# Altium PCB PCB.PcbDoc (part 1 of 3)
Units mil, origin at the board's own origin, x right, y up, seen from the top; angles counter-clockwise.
Board outline 5900 x 2310 mil, 2 copper layers (Top Layer, Bottom Layer), stack 62 mil thick; 158 components, 83 nets, 407 pads, 547 vias.
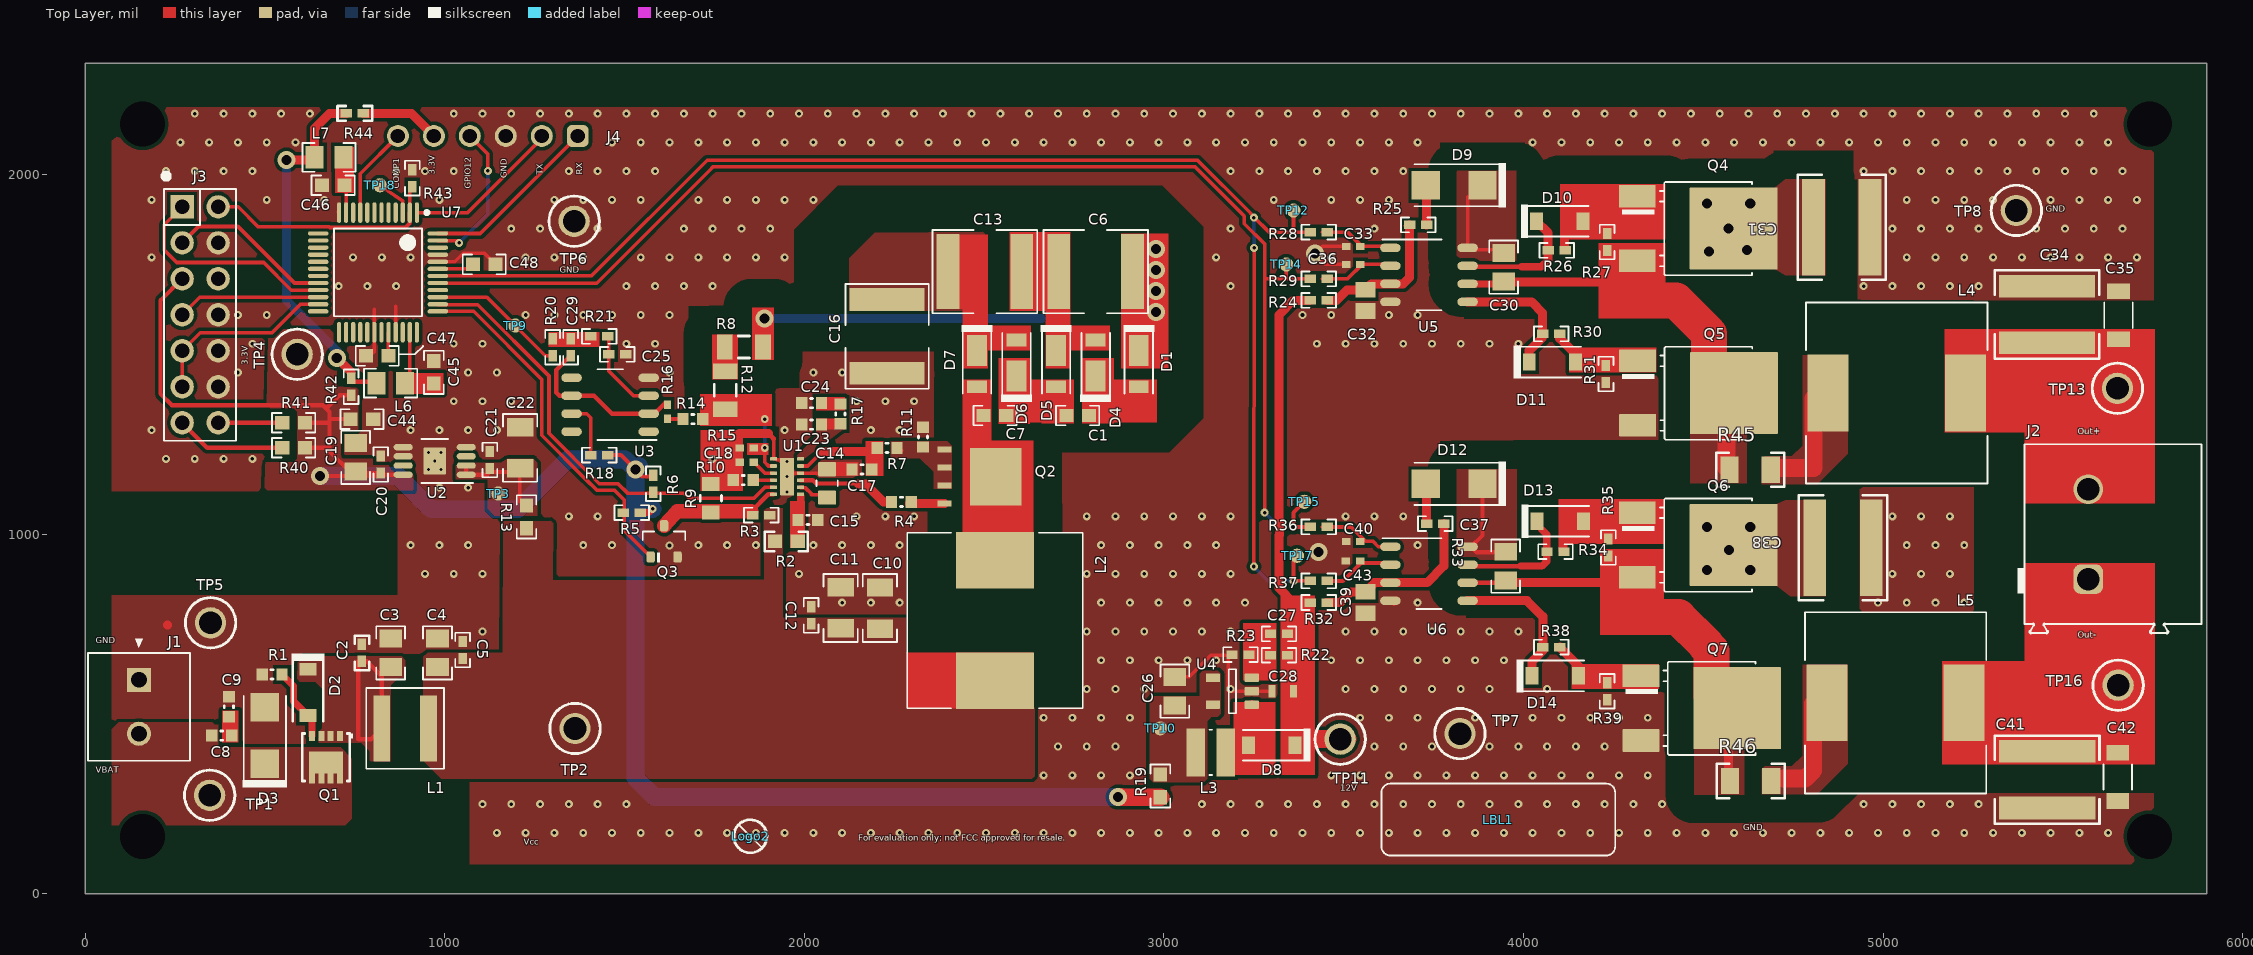
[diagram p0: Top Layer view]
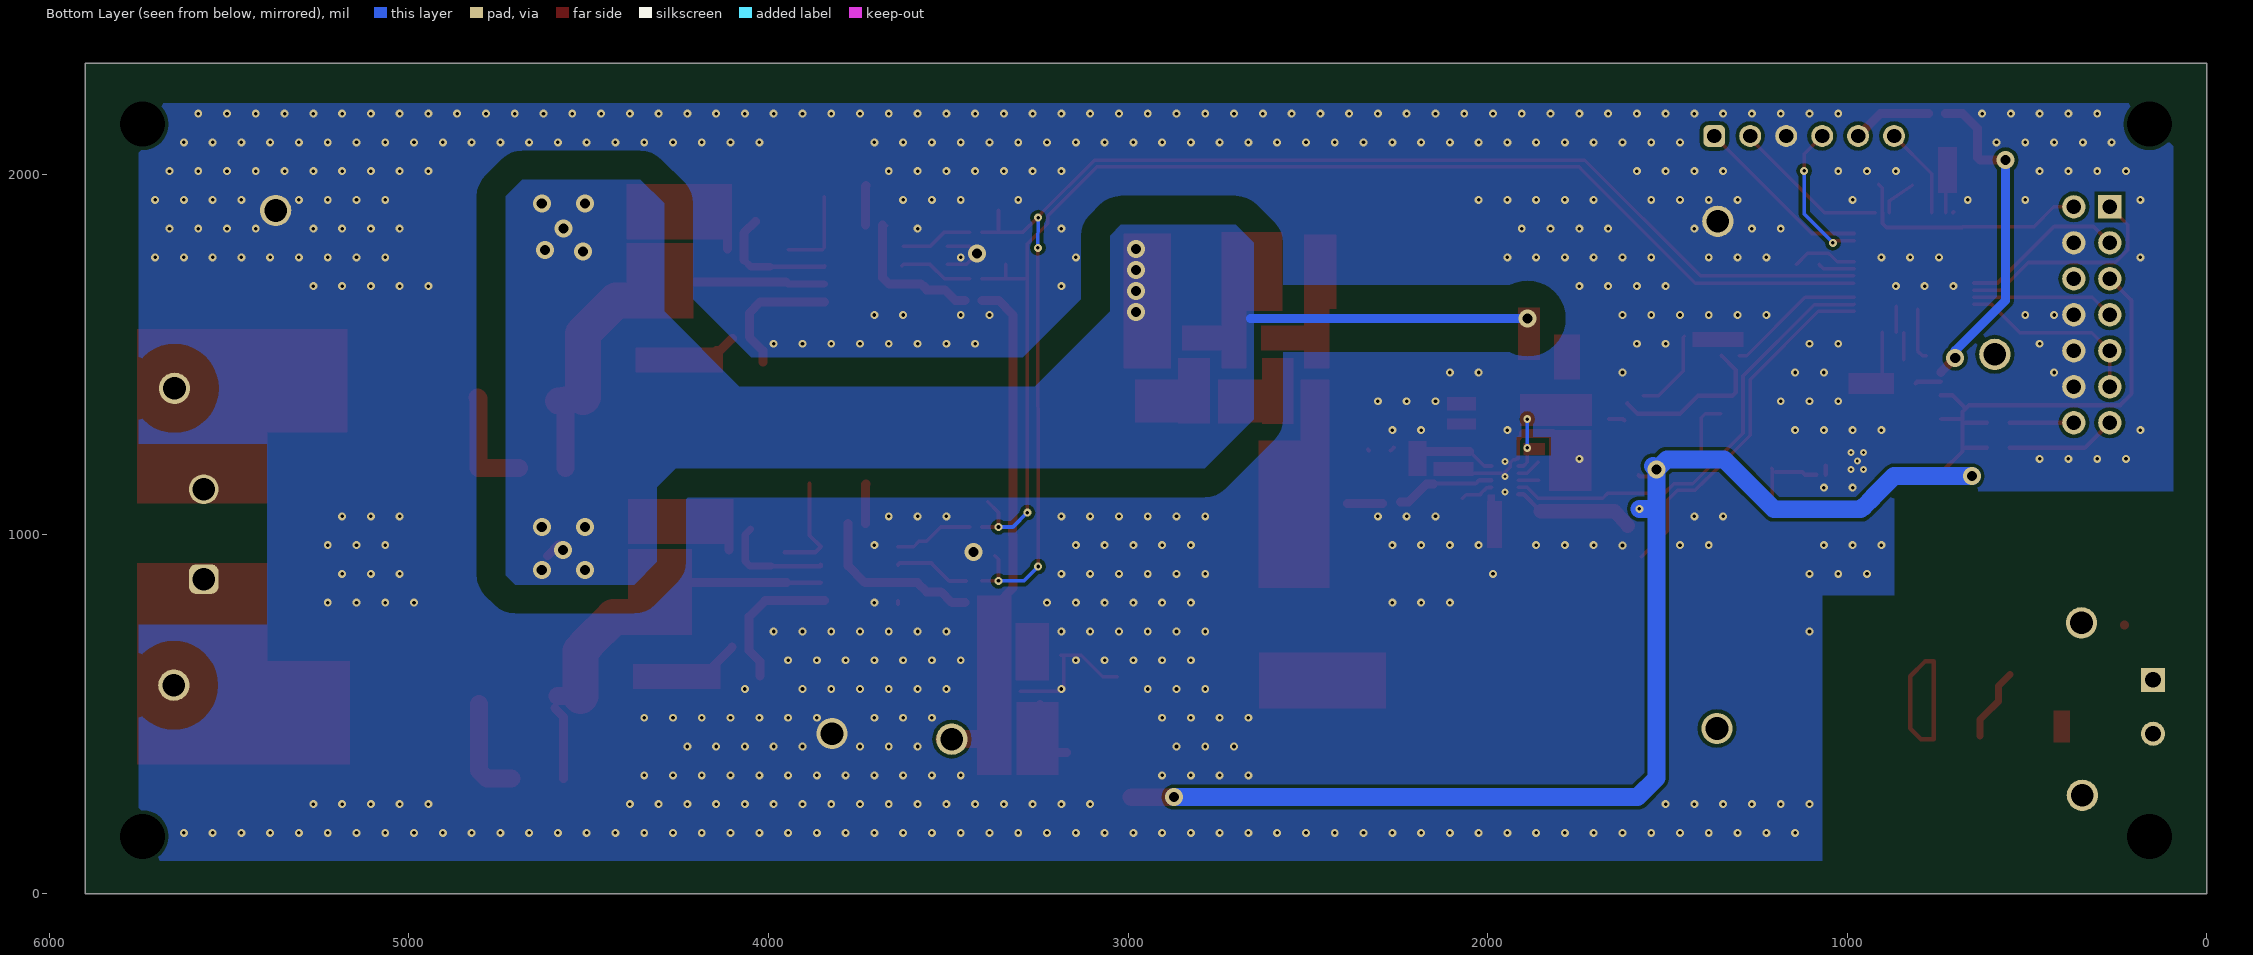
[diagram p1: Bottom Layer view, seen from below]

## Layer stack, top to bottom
Top Solder: solder mask 0.4, Solder Resist, Dk 3.5
Top Layer: signal copper 1.4
Dielectric1: core 59.2, FR-4, Dk 4.8
Bottom Layer: signal copper 1.4
Bottom Solder: solder mask 0.4, Solder Resist, Dk 3.5

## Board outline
0,0 0,2310 5900,2310 5900,0

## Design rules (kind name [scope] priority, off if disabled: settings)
AcuteAngle [All] p1: minimum=4.50000000000000E+0001 checktracksonly=FALSE
AssemblyTestPointUsage [All] p1: valid=2
BoardOutlineClearance BoardOutlineClearance_MountingHoles [OnCopper and InComponentClass('Mounting Holes')] p1: gap=40 ignorepadtopadclearanceinfootprint=FALSE
BoardOutlineClearance BoardOutlineClearance_Poly [OnCopper and IsPoly] p2: gap=25 ignorepadtopadclearanceinfootprint=FALSE
BoardOutlineClearance [OnCopper and Not InComponentClass('Logo') and not InComponentClass('FiducialMark') and not InRegion(1000,500,4000,800) and not InPoly] p3: gap=75 ignorepadtopadclearanceinfootprint=FALSE
Clearance Clearance_HV_Signal_GND [InNetClass('HV_Signal') vs InNet('GND')] p1: gap=80 ignorepadtopadclearanceinfootprint=FALSE
Clearance Clearance_HV_LV_Bridge [InNet('HV') vs InNetClass('LV_Bridge')] p2: gap=80 ignorepadtopadclearanceinfootprint=FALSE
Clearance Clearance_HV_Bridge_LV_Bridge [InNetClass('HV_Bridge') vs InNetClass('LV_Bridge')] p3: gap=80 ignorepadtopadclearanceinfootprint=FALSE
Clearance Clearance_HV_Bridge_GND [InNetClass('HV_Bridge') vs InNet('GND')] p4: gap=80 ignorepadtopadclearanceinfootprint=FALSE
Clearance Clearance_HV_CP_GND [InNetClass('HV_CP') vs InNet('GND')] p5: gap=80 ignorepadtopadclearanceinfootprint=FALSE
Clearance Clearance_HV_GND [InNet('HV') vs InNet('GND')] p6: gap=90 ignorepadtopadclearanceinfootprint=FALSE
Clearance Clearance_Keepouts [((IsTrack Or IsArc) And Not InPoly) And IsFree and IsKeepOut vs ((IsTrack Or IsArc) And Not InPoly) And IsFree and IsKeepOut] p7: gap=0 ignorepadtopadclearanceinfootprint=FALSE
Clearance Clearance_Poly [InPolygon] p8: gap=10 ignorepadtopadclearanceinfootprint=FALSE
Clearance Clearance_FiducialMark [IsKeepOut and InComponentClass('FiducialMark') vs IsPad and InComponentClass('FiducialMark')] p9: gap=0 ignorepadtopadclearanceinfootprint=FALSE
Clearance [All] p10: gap=7.87 ignorepadtopadclearanceinfootprint=FALSE except(0: Arc-Hole Track-Hole SMDPad-Hole THPad-Hole Via-Hole Fill-Hole Poly-Hole Region-Hole Text-Hole)
ComponentClearance ComponentClearance_MountingHoles_FiducialMarks [InComponentClass('Mounting Holes') vs InComponentClass('FiducialMark')] p1: gap=50 collisioncheckmode=3 verticalgap=10 showdistances=FALSE
ComponentClearance ComponentClearance_Shunt [InComponentClass('Header') vs InComponentClass('Shunt')] p2: gap=0 collisioncheckmode=3 verticalgap=0 showdistances=FALSE
ComponentClearance ComponentClearance_Logo [InComponentClass('Logo')] p3: gap=50 collisioncheckmode=3 verticalgap=10 showdistances=FALSE
ComponentClearance ComponentClearance_ScrewToNut [(HasFootprint('NY PMS 440 0025 PH')) vs (HasFootprint('Keystone_1902C'))] p4: gap=5 collisioncheckmode=3 verticalgap=10 showdistances=FALSE
ComponentClearance ComponentClearance_MountingHoles [InComponentClass('Mounting Holes')] p5: gap=250 collisioncheckmode=3 verticalgap=100000 showdistances=FALSE
ComponentClearance ComponentClearance_SmallPassives [HasFootprint('0201*') or HasFootprint('0402*') or HasFootprint('0508') or HasFootprint('0603*') or HasFootprint('0612') or HasFootprint('0805*') or HasFootprint('0815*') or HasFootprint('0830*') or HasFootprint('1206*') or HasFootprint('1210*') or HasFootprint('1808*') or HasFootprint('1812*') or HasFootprint('1825*') or HasFootprint('2010*') or HasFootprint('2220*') or HasFootprint('2225*') or HasFootprint('2512*') or HasFootprint('2728*') or HasFootprint('3518*') vs HasFootprint('0201*') or HasFootprint('0402*') or HasFootprint('0508') or HasFootprint('0603*') or HasFootprint('0612') or HasFootprint('0805*') or HasFootprint('0815*') or HasFootprint('0830*') or HasFootprint('1206*') or HasFootprint('1210*') or HasFootprint('1808*') or HasFootprint('1812*') or HasFootprint('1825*') or HasFootprint('2010*') or HasFootprint('2220*') or HasFootprint('2225*') or HasFootprint('2512*') or HasFootprint('2728*') or HasFootprint('3518*')] p6: gap=14.96 collisioncheckmode=3 verticalgap=10 showdistances=FALSE
ComponentClearance ComponentClearance_THtoSMT [IsThruComponent vs IsSMTComponent] p7: gap=40 collisioncheckmode=3 verticalgap=30 showdistances=FALSE
ComponentClearance ComponentClearance_THtoTH [IsThruComponent vs IsThruComponent] p8: gap=30 collisioncheckmode=3 verticalgap=30 showdistances=FALSE
ComponentClearance [All] p9: gap=30 collisioncheckmode=3 verticalgap=10 showdistances=FALSE
DiffPairsRouting [All] p1: maxlimit=100 minlimit=10 mostfreqgap=10 toplayer_minwidth=15 toplayer_maxwidth=15 toplayer_prefwidth=15 bottomlayer_minwidth=15 bottomlayer_maxwidth=15 bottomlayer_prefwidth=15 maxuncoupledlength=1000
FabricationTestPointUsage TestPointUsage [All] p1: valid=2 allowmultiple=FALSE
FabricationTestpoint Testpoint [All] p1: side=3 testpointundercomponent=TRUE minsize=40 maxsize=100 preferedsize=60 minholesize=0 maxholesize=40 preferedholesize=32 testpointgrid=1 allowsidetop=TRUE allowsidebottom=TRUE usegrid=TRUE gridtolerance=0.01
FanoutControl Fanout_LCC [IsLCC] p1: bgadir=Out bgaviamode=Centered fanoutstyle=Auto fanoutdirection=Alternating viagrid=1 // Fanout_LCC (Default Rule)
FanoutControl Fanout_BGA [IsBGA] p2: bgadir=Out bgaviamode=Centered fanoutstyle=Auto fanoutdirection=Alternating viagrid=1 // Fanout_BGA (Default Rule)
FanoutControl Fanout_Default [All] p4: bgadir=Out bgaviamode=Centered fanoutstyle=Auto fanoutdirection=Alternating viagrid=1 // Fanout_Default (Default Rule)
FanoutControl Fanout_Small [(CompPinCount < 5)] p5: bgadir=Out bgaviamode=Centered fanoutstyle=Auto fanoutdirection=OutThenIn viagrid=1 // Fanout_Small (Default Rule)
HoleSize [All] p1: absolutevalues=TRUE maxlimit=251 minlimit=7.87 maxpercent=80.000 minpercent=20.000
MinimumAnnularRing MinimumAnnularRing_ThermalPadVias [IsVia and InAnyComponent] p1: minimumring=5.91
MinimumAnnularRing [All] p2: minimumring=5
MinimumSolderMaskSliver MinimumSolderMaskSliver_Logo [InComponentClass('Logo') vs InComponentClass('Logo')] p1: minsoldermaskwidth=0.7
MinimumSolderMaskSliver [All] p2: minsoldermaskwidth=3.94
PlaneClearance [All] p1: clearance=10
PlaneConnect [All] p1: planeconnectstyle=Relief reliefexpansion=10 reliefentries=4 reliefconductorwidth=10 reliefairgap=10
PolygonConnect [All] p1: connectstyle=Direct reliefconductorwidth=10 reliefentries=4 polygonreliefangle="90 Angle" airgapwidth=10
RoutingVias ThermalPadVias [IsVia and InAnyComponent] p1: holewidth=7.87 width=19.68 viastyle="Through Hole" minholewidth=7.87 minwidth=19.68 maxholewidth=12.99 maxwidth=23.62
RoutingVias [All] p2: holewidth=16 width=34 viastyle="Through Hole" minholewidth=7.87 minwidth=20 maxholewidth=40 maxwidth=65
SilkToBoardRegionClearance [Not ((IsComment or IsDesignator) And (Hide <> 'False')) and not InRegion(1000,500,4000,800)] p1:
SilkToSilkClearance SilkToSilkClearance_Pb-FreeLogo [(HasFootprint('Pb-Free_Overlay_Medium') OR HasFootprint('Pb-Free_Overlay_Small')) vs (HasFootprint('Pb-Free_Overlay_Medium') OR HasFootprint('Pb-Free_Overlay_Small'))] p1: silktosilkclearance=0
SilkToSilkClearance [All] p2: silktosilkclearance=1
SilkToSolderMaskClearance SilkToComponentPadClearance [(IsPad or IsFill or IsRegion) and InAnycomponent] p1: minsilkscreentomaskgap=3 clearancetoexposedcopper=TRUE
SilkToSolderMaskClearance "Silk to Solder Mask Opening" [All] p2: minsilkscreentomaskgap=4 clearancetoexposedcopper=FALSE
SolderMaskExpansion [All] p1: expansion=1.97
Width [All] p1: maxlimit=100 minlimit=6 preferedwidth=10 checkconnectedcopper=TRUE
14 further rules are at their usual default settings.

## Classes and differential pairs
net class HV_Bridge: NetC30_1 NetC30_2 NetC37_1 NetC37_2 NetD10_1 NetD10_2 NetD13_1 NetD13_2
component class Pg3: C44 C45 C46 C47 C48 J3 J4 L6 L7 R40 R41 R42 R43 R44 TP18 U7
component class Pg2: C30 C31 C32 C33 C34 C35 C36 C37 C38 C39 C40 C41 C42 C43 D9 D10 D11 D12 D13 D14 J2 L4 L5 Q4 Q5 Q6 R24 R25 R26 R27 R28 R29 R30 R31 R32 R33 R34 R35 R36 R37 R38 R39 R45 R46 TP12 TP13 TP14 TP15 TP16 TP17 U5 U6
component class Pg1: C1 C2 C3 C4 C5 C6 C7 C8 C9 C10 C11 C12 C13 C14 C15 C16 C17 C18 C19 C20 C21 C22 C23 C24 C25 C26 C27 C28 C29 D1 D2 D3 D4 D5 D6 D7 D8 J1 L1 L2 L3 Q1 Q2 Q3 Q? R1 R2 R3 R4 R5 R6 R7 R8 R9 R10 R11 R12 R13 R14 R15 R16 R17 R18 R19 R20 R21 R22 R23 R? TP1 TP2 TP3 TP4 TP5 TP6 TP7 TP8 TP9 TP10 TP11 U1 U2 U3 U4
component class EVM_Hardware: LBL1 Logo1 Logo2 Logo3 ZZ1 ZZ2 ZZ3 ZZ4
component class AssemblyNote: ZZ1 ZZ2 ZZ3 ZZ4
component class Label: LBL1
component class Header: J3 J4
net class HV_CP: HV NetC1_1 NetC1_2 NetC6_2 NetC7_2 NetC13_2 NetR8_1
net class LV_Bridge: GND NetD11_2 NetD14_2
net class LV_Bridge_Pins: GND NetD11_1 NetD14_1
net class HV_Signal: NetC34_1 NetC41_1 NetL4_1 NetL5_1

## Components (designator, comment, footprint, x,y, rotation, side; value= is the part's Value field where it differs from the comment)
C1 "HMK107B7104KAHT" 0603 2760,1330 r180 top value=0.1uF
C2 "GCM155R71H104KE02D" 0402 770,670 r90 top value=0.1uF
C3 "CGA4J3X7R1H684K125AB" 0805_HV 850,670 r90 top value=0.68uF
C4 "CGA4J3X7R1H684K125AB" 0805_HV 980,670 r90 top value=0.68uF
C5 "GCM155R71H104KE02D" 0402 1050,678 r90 top value=0.1uF
C6 "CGA9M3X7S2A685K200KB" 2220_220 2810,1730 r180 top value=6.8uF
C7 "HMK107B7104KAHT" 0603 2530,1330 r180 top value=0.1uF
C8 "CGA3E2X7R2A472K080AA" 0603L 380,440 r0 top value=4700pF
C9 "CGA3E2X7R2A472K080AA" 0603L 400,520 r270 top value=4700pF
C10 "CGA5L3X5R1H106M160AB" 1206 2210.32,794.5 r90 top value=10uF
C11 "CGA5L3X5R1H106M160AB" 1206 2101,795 r90 top value=10uF
C12 "GCM155R71H104KE02D" 0402 2018.65,774.12 r90 top value=0.1uF
C13 "CGA9M3X7S2A685K200KB" 2220_220 2502.05,1730 r180 top value=6.8uF
C14 "CGA4J3X7R1H105K125AB" 0805_HV1 2063.3,1141.13 r270 top value=1uF
C15 "CGA3E2NP01H101J080AA" 0603L 2010,1040 r0 top value=100pF
C16 "CGA9M3X7S2A685K200KB" 2220_220 2230,1550 r270 top value=6.8uF
C17 "CGA3E2NP01H101J080AA" 0603L 2160,1180 r180 top value=100pF
C18 "CGA2B3X7R1H103K050BB" 0402L 1840,1200 r180 top value=0.01uF
C19 "CGA4J1X7R1V475K125AC" 0805_HV 752.6,1213.62 r90 top value=4.7uF
C20 "GCM155R71H104KE02D" 0402 822.28,1193.62 r90 top value=0.1uF
C21 "GCM155R71H104KE02D" 0402 1125.5,1206.24 r90 top value=0.1uF
C22 "CGA5L3X5R1H106M160AB" 1206 1210,1240 r90 top value=10uF
C23 "CGA3E2X7R2A223K080AA" 0603L 2020,1304.43 r180 top value=0.022uF
C24 "CGA3E3X7S2A333K080AB" 0603L 2020,1364.43 r180 top value=0.033uF
C25 "CGA2B3X7R1H103K050BB" 0402 1480,1500 r0 top value=0.01uF
C26 "CGA4J1X7R1V475K125AC" 0805_HV 3030,563.29 r90 top value=4.7uF
C27 "CGA2B3X7R1H103K050BB" 0402 3320,722.5 r180 top value=0.01uF
C28 "CGA3E1X7R1E105K080AC" 0603S 3330,563.29 r180 top value=1uF
C29 "CGA2B3X7R1H223K050BB" 0402 1350,1520 r90 top value=0.022uF
C30 "CGA4J2X7R1H224K125AA" 0805_HV 3944.34,1742.25 r90 top value=0.22uF
C31 "1825PC105KAT1A" 1825_254 4884.5,1853.5 r0 top value=1uF
C32 "CGA4J1X7R1E475K125AC" 0805L 3560,1650 r270 top value=4.7uF
C33 "C0402C330J5GACAUTO" 0402L 3526.37,1800 r180 top value=33pF
C34 "1825PC105KAT1A" 1825_254 5455,1611 r90 top value=1uF
C35 "CGA5L4X7T2W104M160AA" 1206_180 5654,1608.5 r90 top value=0.1uF
C36 "C0402C330J5GACAUTO" 0402L 3526.37,1750 r180 top value=33pF
C37 "CGA4J2X7R1H224K125AA" 0805_HV 3950,911.12 r90 top value=0.22uF
C38 "1825PC105KAT1A" 1825_254 4888,962 r0 top value=1uF
C39 "CGA4J1X7R1E475K125AC" 0805L 3560,810 r270 top value=4.7uF
C40 "C0402C330J5GACAUTO" 0402L 3526.37,980 r180 top value=33pF
C41 "1825PC105KAT1A" 1825_254 5455.5,317.5 r270 top value=1uF
C42 "CGA5L4X7T2W104M160AA" 1206_180 5652,325 r270 top value=0.1uF
C43 "C0402C330J5GACAUTO" 0402L 3525.75,925.03 r180 top value=33pF
C44 "CL10B105KP8VPNC" 0603 770,1320 r0 top value=1uF
C45 "GCM188R70J225KE22D" 0603 970,1450 r90 top value=2.2uF
C46 "GCM188R70J225KE22D" 0603 690,1970 r180 top value=2.2uF
C47 "GCM188R70J225KE22D" 0603 812.47,1495.75 r180 top value=2.2uF
C48 "GCM188R70J225KE22D" 0603 1110,1750 r0 top value=2.2uF
D1 "DFLS1100Q-7" PowerDI123 2930,1460 r270 top value=100V
D2 "BZT52C16-7-F" SOD-123 620,560 r270 top value=16V
D3 "P4SMA18CA-E3/61" SMA 500,440 r90 top value=18V
D4 "DFLS1100Q-7" PowerDI123 2810,1490 r90 top value=100V
D5 "DFLS1100Q-7" PowerDI123 2700,1460 r270 top value=100V
D6 "DFLS1100Q-7" PowerDI123 2590,1490 r90 top value=100V
D7 "DFLS1100Q-7" PowerDI123 2480,1460 r270 top value=100V
D8 "MBR0520LT1G" SOD-123 3300,413.29 r180 top value=20V
D9 "MURA160T3G" SMA 3806.77,1970 r180 top value=600V
D10 "BAT46W-E3-08" SOD-123 4100,1870 r0 top value=100V
D11 "BAT46W-E3-08" SOD-123 4080.03,1478.5 r0 top value=100V
D12 "MURA160T3G" SMA 3806.77,1140 r180 top value=600V
D13 "BAT46W-E3-08" SOD-123 4101.5,1036 r0 top value=100V
D14 "BAT46W-E3-08" SOD-123 4088,605.98 r0 top value=100V
J1 "1727010" PhoenixConact_1727010 150,520 r270 top
J2 "OSTT7020150" On-Shore_OSTT7020150 5570,1000 r90 top
J3 "PEC07DAAN" CONN_PEC07DAAN 320,1610 r270 top
J4 "TSW-106-07-T-S" Samtec_TSW-106-07-T-S 1120,2107.12 r180 top
L1 "XAL5030-222MEB" XAL5030 890,460 r0 top value=2.2uH
L2 "MSS1260T-273MLB" MSS1260T 2530,760 r90 top value=27uH
L3 "78438335220" WE-MAIA_3015 3130,393.29 r0 top value=22uH
L4 "SRR1260A-331K" SRR1260A 5037.5,1392.5 r0 top value=330uH
L5 "SRR1260A-331K" SRR1260A 5034,531 r0 top value=330uH
L6 "742792063" 0805_HV 850,1420 r180 top value="60 ohm"
L7 "782853221" 0805_HV 678.35,2047.8 r180 top value="220 ohm"
LBL1 "THT-14-423-10" Label_650x200 3929.5,206.5 r180 top
Logo2 "Pb-Free Symbol" Pb-Free_Overlay_Small 1850,160 r0 top
Logo3 "FCC disclaimer" FCC_disclaimer 830,2810 r0 top
Q1 "DMP3035SFG-7" PowerDI3333-8 670,380 r270 top value=-30V
Q2 "SQJA68EP-T1_GE3" PowerPAK_SO-8L 2500,1160 r0 top value=100V
Q3 "BSS806NEH6327XTSA1" SOT-23L 1610,980 r90 top value=20V
Q4 "IPD5N25S3430ATMA1" DPAK 4450,1850 r0 top value=250V
Q5 "IPD5N25S3430ATMA1" DPAK 4450.86,1392.24 r0 top value=250V
Q6 "IPD5N25S3430ATMA1" DPAK 4450,970 r0 top value=250V
Q7 "IPD5N25S3430ATMA1" DPAK 4460,516.22 r0 top value=250V
R1 "CRCW06031K50FKEA" 0603L 520,610 r0 top value=1.50k
R2 "CRCW060310R0FKEAHP" 0603 1950,980 r0 top value=10.0
R3 "CRCW04026K34FKED" 0402 1880.5,1053 r0 top value=6.34k
R4 "RCS06030000Z0EA" 0603L 2270,1090 r0 top value=0
R5 "CRCW0402511KFKED" 0402 1520,1060 r0 top value=511k
R6 "CRCW0402511KFKED" 0402 1580,1140 r90 top value=511k
R7 "CRCW060310R0FKEAHP" 0603L 2230,1240 r0 top value=10.0
R8 "ERJ-8ENF2003V" 1206L 1832,1520.5 r0 top value=200k
R9 "ERJ-6ENF1691V" 0805_HV1 1740,1100 r270 top value=1.69k
R10 "CRCW06039K09FKEA" 0603L 1830,1150 r0 top value=9.09k
R11 "ERJ-L03KF50MV" 0603L 2330,1270 r270 top value=0.05
R12 "ERJ-8ENF1023V" 1206L 1780,1400 r90 top value=102k
R13 "RCS06030000Z0EA" 0603 1227.5,1048 r270 top value=0
R14 "CRCW06034K02FKEA" 0603L 1690,1320 r180 top value=4.02k
R15 "ERJ-2RKF2401X" 0402L 1840,1240 r0 top value=2.40k
R16 "CRCW04020000Z0EDHP" 0402L 1620,1340 r270 top value=0
R17 "CRCW060319K6FKEA" 0603L 2100,1334.43 r270 top value=19.6k
R18 "CRCW04020000Z0EDHP" 0402 1430,1220 r0 top value=0
R19 "RCS06030000Z0EA" 0603 2990,300 r270 top value=0
R20 "CRCW04027K87FKED" 0402 1300,1520 r90 top value=7.87k
R21 "CRCW040214K7FKED" 0402 1430,1550 r0 top value=14.7k
R22 "CRCW04021M50FKED" 0402 3320,663.29 r0 top value=1.50Meg
R23 "CRCW0402174KFKED" 0402 3212.79,665 r0 top value=174k
R24 "CRCW04020000Z0EDHP" 0402 3430,1650 r180 top value=0
R25 "CRCW04022R21FKED" 0402 3706.77,1860 r0 top value=2.21
R26 "CRCW04023R32FKED" 0402 4092,1789 r0 top value=3.32
R27 "CRCW040210K2FKED" 0402 4232,1812.5 r90 top value=10.2k
R28 "CRCW040249R9FKED" 0402 3430,1840 r0 top value=49.9
R29 "CRCW040249R9FKED" 0402 3430,1710 r0 top value=49.9
R30 "CRCW04023R32FKED" 0402 4077,1557 r0 top value=3.32
R31 "CRCW040210K2FKED" 0402 4229,1445.5 r90 top value=10.2k
R32 "CRCW04020000Z0EDHP" 0402 3430,810 r180 top value=0
R33 "CRCW04022R21FKED" 0402 3754.5,1029.5 r180 top value=2.21
R34 "CRCW04023R32FKED" 0402 4088.81,951.5 r0 top value=3.32
R35 "CRCW040210K2FKED" 0402 4235.73,963 r90 top value=10.2k
R36 "CRCW040249R9FKED" 0402 3430,1020 r0 top value=49.9
R37 "CRCW040249R9FKED" 0402 3430,870 r0 top value=49.9
R38 "CRCW04023R32FKED" 0402 4077,686 r0 top value=3.32
R39 "CRCW040210K2FKED" 0402 4232,562.97 r90 top value=10.2k
R40 "CRCW06034K70JNEA" 0603 580,1240 r0 top value=4.7k
R41 "CRCW06034K70JNEA" 0603 580,1310 r0 top value=4.7k
R42 "CRCW04020000Z0EDHP" 0402 740,1410 r90 top value=0
R43 "RMCF0402FT2K20" 0402 910,1990 r270 top value=2.20k
R44 "CRCW04021K02FKED" 0402 750,2170 r0 top value=1.02k
R45 "CRCW120618R0JNEA" 1206 4629.5,1179 r0 top value=18
R46 "CRCW120618R0JNEA" 1206 4631,313.5 r0 top value=18
TP1 "5010" Keystone5010 346.5,274 r270 top
TP2 "5010" Keystone5010 1362.5,459.69 r90 top
TP3 "TP_SM_1MM" TP_SM_1MM 1149,1113 r270 top
TP4 "5010" Keystone5010 590,1500 r270 top
TP5 "5011" Keystone5011 349,753.5 r0 top
TP6 "5011" Keystone5011 1360,1870 r0 top
TP7 "5011" Keystone5011 3823,445.5 r0 top
TP8 "5011" Keystone5011 5370,1900 r0 top
TP9 "TP_SM_1MM" TP_SM_1MM 1196.38,1580 r90 top
TP10 "TP_SM_1MM" TP_SM_1MM 2990,460 r0 top
TP11 "5010" Keystone5010 3490,430 r180 top
TP12 "TP_SM_1MM" TP_SM_1MM 3360,1900 r90 top
TP13 "5127" Keystone5127 5651,1405.5 r0 top
TP14 "TP_SM_1MM" TP_SM_1MM 3340,1750 r90 top
TP15 "TP_SM_1MM" TP_SM_1MM 3390,1090 r90 top
TP16 "5127" Keystone5127 5653,580 r0 top
TP17 "TP_SM_1MM" TP_SM_1MM 3370,940 r90 top
TP18 "TP_SM_1MM" TP_SM_1MM 820,1970 r90 top
U1 "LM5155QDSSTQ1" DSS0012C 1952.05,1160 r180 top
U2 "TPS7B8233QDGNRQ1" DGN0008D_N 972.28,1203.62 r180 top
U3 "TLV271QDRQ1" D0008A_N 1460,1360 r180 top
U4 "TPS61041QDBVRQ1" DBV0005A_N 3190,563.29 r180 top
U5 "UCC27712QDRQ1" D0008A_N 3736.77,1720.87 r0 top
U6 "UCC27712QDRQ1" D0008A_N 3736.77,890 r0 top
U7 "TMS320F28027PTQ" PT0048A_N 814.52,1727.8 r270 top
ZZ1 "This Assembly Note is for PCB labels only" AssemblyNoteLabel 4843.5,5612 r90 top
ZZ2 "These assemblies are ESD sensitive, ESD precautions shall be observed." AssemblyNote 4816,5725.5 r0 top
ZZ3 "These assemblies must be clean and free from flux and all contaminants. Use of no clean flux is not acceptable." AssemblyNote 4816,5839.5 r0 top
ZZ4 "These assemblies must comply with workmanship standards IPC-A-610 Class 2, unless otherwise specified." AssemblyNote 4814,5943 r0 top

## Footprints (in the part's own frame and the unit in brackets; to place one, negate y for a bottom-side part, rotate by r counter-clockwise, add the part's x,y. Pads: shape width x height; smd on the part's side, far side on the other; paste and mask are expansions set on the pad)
0402 [mm] "0402 from SM-752 data"
  rect 0.8x0.6 smd: 1(-0.6,0) 2(0.6,0)
  silkscreen extent -1.22,-0.52 1.22,0.52, body extent -0.55,-0.3 0.55,0.3, height 0.6
0402L [mm] "0402 from SM-752 data"
  rect 0.6x0.5 smd: 1(-0.5,0) 2(0.5,0)
  body extent -0.55,-0.3 0.55,0.3, height 0.6
0603 [mm] "0603 from SM-752 data"
  rect 1x0.95 smd: 1(-0.8,0) 2(0.8,0)
  silkscreen extent -1.52,-0.69 1.52,0.69, body extent -0.87,-0.47 0.87,0.47, height 1
0603L [mm] "0603 from SM-752 data"
  rect 0.8x0.85 smd: 1(-0.7,0) 2(0.7,0)
  silkscreen extent -0.07,-0.33 0.07,0.33, body extent -0.87,-0.47 0.87,0.47, height 1
0603S [mil]
  rect 20x35 smd: 1(-30,0) 2(30,0)
  body extent -34,-19 34,19, height 39
0805_HV [mil] "0805 with 30mil clearance between pads"
  rect 50x63 smd: 1(-40,0) 2(40,0)
  silkscreen extent -74,-40 74,40, body extent -43,-29 43,29, height 57
0805_HV1 [mm] "Custom footprint based on analyzing multiple manufacturer recommendations"
  rrect10% 1x1.25 smd: 1(-1,0) 2(1,0)
  silkscreen extent -0.2,-0.75 0.2,0.75, body extent -1.1,-0.72 1.1,0.73, height 1.45
0805L [mm] "0805 from SM-752 data"
  rect 1.1x1.4 smd: 1(-0.75,0) 2(0.75,0)
  body extent -1.1,-0.72 1.1,0.72, height 1.45
1206 [mm] "1206 from SM-752 data"
  rect 1.3x1.85 smd: 1(-1.45,0) 2(1.45,0)
  silkscreen extent -2.4,-1.21 2.4,1.21, body extent -1.7,-0.9 1.7,0.9, height 1.35
1206_180 [mm] "1206_180"
  rect 1.1x1.6 smd: 1(-1.7,0) 2(1.7,0)
  silkscreen extent -0.9,-1 0.9,1, body extent -1.75,-0.95 1.75,0.95, height 1.8
1206L [mm] "1206 from SM-752 data"
  rect 1.1x1.75 smd: 1(-1.35,0) 2(1.35,0)
  silkscreen extent -0.4,-0.77 0.4,0.77, body extent -1.7,-0.9 1.7,0.9, height 1.35
1825_254 [mm] "Chip Capacitor, Body 4.5x6.4mm, IPC Medium Density"
  rect 1.6x6.8 smd: 1(-2,0) 2(2,0)
  silkscreen extent -3.11,-3.7 3.11,3.7, body extent -2.4,-3.4 2.4,3.4, height 2.54
2220_220 [mm] "Chip Capacitor, Body 5.7x5.0mm, IPC Medium Density"
  rect 1.6x5.3 smd: 1(-2.6,0) 2(2.6,0)
  silkscreen extent -3.69,-2.94 3.69,2.94, body extent -2.95,-2.62 2.95,2.62, height 2.2
AssemblyNote [mil] "Assembly Note"
AssemblyNoteLabel [mil] "Assembly Note for PCB Labels"
CONN_PEC07DAAN [mm] "SULLINS"
  rect 1.65x1.65 hole 1.016 mask+0: 1(-7.62,-1.27)
  round 1.65 hole 1.016 mask+0: 2(-7.62,1.27) 3(-5.08,-1.27) 4(-5.08,1.27) 5(-2.54,-1.27) 6(-2.54,1.27) 7(0,-1.27) 8(0,1.27) 9(2.54,-1.27) 10(2.54,1.27) 11(5.08,-1.27) 12(5.08,1.27) 13(7.62,-1.27) 14(7.62,1.27)
  silkscreen extent -9.99,-2.6 8.89,2.54, body extent -8.95,-2.6 8.95,2.6, height 8.38
D0008A_N [mm] "SOIC, 8-Leads, Body 4.9x3.9mm, Pitch 1.27mm, IPC Medium Density"
  oval 1.45x0.6 smd: 1(-2.725,1.905) 2(-2.725,0.635) 3(-2.725,-0.635) 4(-2.725,-1.905) 5(2.725,-1.905) 6(2.725,-0.635) 7(2.725,0.635) 8(2.725,1.905)
  silkscreen extent -3.3,-2.5 0.9,2.5, body extent -3,-2.45 3,2.45, height 1.63
DBV0005A_N [mm] "SOT23, 5-Leads, Body 2.9x1.6mm, Pitch 0.95mm, Lead Span 2.8mm, IPC Medium Density"
  rrect17% 1x0.6 smd: 1(-1.375,0.95) 2(-1.375,0) 3(-1.375,-0.95) 4(1.375,-0.95) 5(1.375,0.95)
  silkscreen extent -0.25,-1.55 0.25,1.55, body extent -1.42,-1.46 1.42,1.46, height 1.09
DGN0008D_N [mm] "TSOP, 8-Leads, Body 3x3mm, Pitch 0.65mm, Thermal Pad 1.89x1.57mm, IPC Medium Density"
  rrect100% 1.35x0.45 smd: 1(-2.225,0.975) 2(-2.225,0.325) 3(-2.225,-0.325) 4(-2.225,-0.975) 5(2.225,-0.975) 6(2.225,-0.325) 7(2.225,0.325) 8(2.225,0.975)
  rrect6% 1.57x1.89 smd: 9(0,0)
  silkscreen extent -2.73,-1.55 0.95,1.55, body extent -2.46,-1.5 2.46,1.5, height 1.1
DPAK [mm] "D-PAK, 3-Pads, Body 6.22x6.73mm (max), TO-252AA using nominal STEP model"
  rrect6% 2.6x1.6 smd: 1(-3.4,2.28) 3(-3.4,-2.28)
  rrect2% 6.2x5.8 smd paste-2.9: 4(3.4,0)
  silkscreen extent -4.5,-3.3 4.7,3.28, body extent -3.86,-3.29 5.84,3.29, height 2.48
DSS0012C [mm] "WSON-12"
  rrect40% 0.5x0.25 smd: 1(-0.95,1.25) 2(-0.95,0.75) 3(-0.95,0.25) 4(-0.95,-0.25) 5(-0.95,-0.75) 6(-0.95,-1.25) 7(0.95,-1.25) 8(0.95,-0.75) 9(0.95,-0.25) 10(0.95,0.25) 11(0.95,0.75) 12(0.95,1.25)
  rrect11% 0.95x1.17 on Top Paste: 13(0,0.685) 13(0,-0.685)
  rrect11% 1x2.65 smd paste-0.5: 13(0,0)
  body extent -1,-1.5 1,1.5, height 0.81
FCC_disclaimer [mil]
Keystone5010 [mil] "Keystone Multipurpose loops"
  round 87 hole 63: 1(0,0)
  silkscreen extent -70,-70 70,70, body extent -63,-63 63,62, height 319
Keystone5011 [mil] "Keystone Multipurpose loops"
  round 87 hole 63: 1(0,0)
  silkscreen extent -70,-70 70,70, body extent -63,-63 63,62, height 319
Keystone5127 [mil] "Keystone Multipurpose loops"
  round 87 hole 63: 1(0,0)
  silkscreen extent -70,-70 70,70, body extent -63,-63 63,62, height 319
Label_650x200 [mil] "Thermal Transfer Label"
  round 1 on Mech13: 0(0,0)
  silkscreen extent -325,-100 325,100, body extent -325,-100 325,100, height 1
MSS1260T [mm] "COILCRAFT"
  rect 4x5.5 smd: 1(-4.25,0) 2(4.25,0)
  silkscreen extent -6.2,-6.2 6.2,6.2, body extent -6.15,-6.15 6.15,6.15, height 6.2
On-Shore_OSTT7020150 [mm] "Terminal Block, 6.35mm, 2x1, TH"
  rrect50% 2.1x2.1 hole 1.6: 1(-3.175,0)
  round 2.1 hole 1.6: 2(3.175,0)
  silkscreen extent -6.98,-8 6.35,5, body extent -6.98,-8 6.35,4.5, height 21.5
Pb-Free_Overlay_Small [mil]
  silkscreen extent -46,-46 46,46
PhoenixConact_1727010 [mm]
  rect 1.7x1.7 hole 1.1: 1(-1.905,0)
  round 1.7 hole 1.1: 2(1.905,0)
  silkscreen extent -4.8,-3.6 3.81,3.6, body extent -3.81,-3.6 3.81,3.7, height 8.52
PowerDI123 [mm] "Diodes Inc recommended land pattern, document number DS30628 Rev. 6-2"
  rect 2.2x1.4 smd: 1(-1.275,0)
  rect 0.9x1.4 smd: 2(1.275,0)
  silkscreen extent -3.1,-1.09 1.76,1.09, body extent -2.38,-0.97 1.52,0.96, height 1
PowerDI3333-8 [mm] "SMD, 8-Leads, Body 3.3x3.3mm, Pitch 0.65mm"
  rect 0.7x0.42 smd: 1(-1.5,0.975) 2(-1.5,0.325) 3(-1.5,-0.325) 4(-1.5,-0.975) 5(1.5,-0.975) 6(1.5,-0.325) 7(1.5,0.325) 8(1.5,0.975)
  rect 1.55x2.37 smd: 9(0.375,0)
  silkscreen extent -1.68,-1.68 1.68,1.9, body extent -1.68,-1.68 1.68,1.68, height 0.86
PowerPAK_SO-8L [mm] "based on Vishay recommended land pattern Document 63818 Feb 7, 2012"
  rect 1x0.41 smd: 1(-2.805,1.905) 2(-2.805,0.635) 3(-2.805,-0.635) 4(-2.805,-1.905)
  rect 3.63x4.061 smd: 5(0.805,0)
  Top Layer region: -0.298,-2.64 0.298,-2.64 0.298,-2.03 -0.298,-2.03
  Top Layer region: -0.297,2.03 0.298,2.03 0.298,2.64 -0.297,2.64
  Top Layer region: 2.615,-2.5 3.125,-2.5 3.125,2.5 2.615,2.5
  body extent -3.07,-2.57 3.08,2.57, height 1.21
PT0048A_N [mm] "Thin QFP, 48-Leads, Body 7x7mm, Pitch 0.5mm, IPC Medium Density"
  oval 1.45x0.3 smd: 1(-4.225,2.75) 2(-4.225,2.25) 3(-4.225,1.75) 4(-4.225,1.25) 5(-4.225,0.75) 6(-4.225,0.25) 7(-4.225,-0.25) 8(-4.225,-0.75) 9(-4.225,-1.25) 10(-4.225,-1.75) 11(-4.225,-2.25) 12(-4.225,-2.75) 25(4.225,-2.75) 26(4.225,-2.25) 27(4.225,-1.75) 28(4.225,-1.25) 29(4.225,-0.75) 30(4.225,-0.25) 31(4.225,0.25) 32(4.225,0.75) 33(4.225,1.25) 34(4.225,1.75) 35(4.225,2.25) 36(4.225,2.75)
  oval 0.3x1.45 smd: 13(-2.75,-4.225) 14(-2.25,-4.225) 15(-1.75,-4.225) 16(-1.25,-4.225) 17(-0.75,-4.225) 18(-0.25,-4.225) 19(0.25,-4.225) 20(0.75,-4.225) 21(1.25,-4.225) 22(1.75,-4.225) 23(2.25,-4.225) 24(2.75,-4.225) 37(2.75,4.225) 38(2.25,4.225) 39(1.75,4.225) 40(1.25,4.225) 41(0.75,4.225) 42(0.25,4.225) 43(-0.25,4.225) 44(-0.75,4.225) 45(-1.25,4.225) 46(-1.75,4.225) 47(-2.25,4.225) 48(-2.75,4.225)
  silkscreen extent -4.35,-3.1 3.1,3.58, body extent -4.51,-4.51 4.51,4.51, height 1.5
Samtec_TSW-106-07-T-S [mm] "Samtec 100mil, 6x1, 230 mil above insulator"
  rrect50% 1.55x1.55 hole 1.02: 1(-6.35,0)
  round 1.55 hole 1.02: 2(-3.81,0) 3(-1.27,0) 4(1.27,0) 5(3.81,0) 6(6.35,0)
  body extent -7.75,-1.27 7.62,1.27, height 8.39
SMA [mm] "Molded Diode, 2-Leads, Body 4.3x2.6mm, IPC Medium Density, based on OnSemi component dimensions and land pattern"
  rect 2x2 smd: 1(-2,0) 2(2,0)
  silkscreen extent -3.66,-1.57 2.79,1.57, body extent -2.6,-1.3 2.6,1.3, height 2.42
SOD-123 [mm] "On Semi recommended land pattern"
  rect 0.915x1.22 smd: 1(-1.637,0) 2(1.637,0)
  silkscreen extent -2.74,-1.17 2.03,1.17, body extent -1.93,-0.9 1.93,0.9, height 1.35
SOT-23L [mm] "SOT23, 3-Leads, Body 2.9x1.3mm, Pitch 0.95mm, Lead Span 2.5mm, IPC High Density"
  rrect50% 0.8x0.6 smd: 1(-1.1,0.95) 2(-1.1,-0.95) 3(1.1,0)
  silkscreen extent -1.5,-1.5 0.7,1.5, body extent -1.16,-1.45 1.21,1.45, height 1
SRR1260A [mil] "Bourns UL"
  rect 114x213 smd: 1(-191,0) 2(191,0)
  silkscreen extent -252,-252 252,252, body extent -252,-252 252,252, height 236
TP_SM_1MM [mm] "1mm Test Point, SMT"
  round 1 smd paste-0.5: 1(0,0)
WE-MAIA_3015 [mm] "SMD, 2-Leads, Body 3x3mm"
  rect 1.3x3.4 smd: 1(-1.05,0) 2(1.05,0)
  silkscreen extent -0.1,-1.6 0.1,1.6, body extent -1.6,-1.6 1.6,1.6, height 1.5
XAL5030 [mil] "Coilcraft XAL5030 12/12/11"
  rect 46x183 smd: 1(-65,0) 2(65,0)
  silkscreen extent -108,-112 108,112, body extent -108,-112 108,112, height 122

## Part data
C1 C7: library part CMP-0081011-1, "CAP, CERM, 0.1 µF, 100 V,+/- 10%, X7R, AEC-Q200 Grade 1, 0603", Cap_Case=0603, Manufacturer="Taiyo Yuden", Supplier Part Number 1=587-6009-1-ND, TempCo=X7R, Tolerance_%=10%, Value2=100V, ValueDisplayed=0.1µF
C2 C5 C12 C20 C21: library part CMP-0006356-2, "CAP, CERM, 0.1 uF, 50 V, +/- 10%, X7R, AEC-Q200 Grade 1, 0402", Cap_Case=0402, Manufacturer=MuRata, Supplier Part Number 1=490-10672-1-ND, TempCo=X7R, Tolerance_%=10%, Value1=Unknown, Value2=50V, ValueDisplayed=0.1uF
C3 C4: library part CMP-0007979-2, "CAP, CERM, 0.68 uF, 50 V, +/- 10%, X7R, AEC-Q200 Grade 1, 0805", Cap_Case=0805, Manufacturer=TDK, Supplier Part Number 1=445-6960-1-ND, TempCo=X7R, Tolerance_%=10%, Value1="0.011711 ohm", Value2=50V, ValueDisplayed=0.68uF
C6 C13 C16: library part CMP-0009407-2, "CAP, CERM, 6.8 uF, 100 V, +/- 10%, X7S, AEC-Q200 Grade 1, 2220", Cap_Case=2220_220, Manufacturer=TDK, Supplier Part Number 1=445-13153-1-ND, TempCo=X7S, Tolerance_%=10%, Value1="0.003492 ohm", Value2=100V, ValueDisplayed=6.8uF
C8 C9: library part CMP-0007088-4, "CAP, CERM, 4700 pF, 100 V, +/- 10%, X7R, AEC-Q200 Grade 1, 0603", Cap_Case=0603, Manufacturer=TDK, Supplier Part Number 1=445-5810-1-ND, TempCo=X7R, Tolerance_%=10%, Value1="0.469862 ohm", Value2=100V, ValueDisplayed=4700pF
C10 C11 C22: library part CMP-0008785-2, "CAP, CERM, 10 uF, 50 V, +/- 20%, X5R, AEC-Q200 Grade 3, 1206", Cap_Case=1206, Manufacturer=TDK, Supplier Part Number 1=445-12883-1-ND, TempCo=X5R, Tolerance_%=20%, Value1=Unknown, Value2=50V, ValueDisplayed=10uF
C14: library part CMP-0007976-2, "CAP, CERM, 1 uF, 50 V, +/- 10%, X7R, AEC-Q200 Grade 1, 0805", Cap_Case=0805, Manufacturer=TDK, Supplier Part Number 1=445-6961-1-ND, TempCo=X7R, Tolerance_%=10%, Value1="0.008782 ohm", Value2=50V, ValueDisplayed=1uF
C15 C17: library part CMP-0007075-4, "CAP, CERM, 100 pF, 50 V, +/- 5%, C0G/NP0, AEC-Q200 Grade 0, 0603", Cap_Case=0603, Manufacturer=TDK, Supplier Part Number 1=445-12386-1-ND, TempCo=C0G/NP0, Tolerance_%=5%, Value1=Unknown, Value2=50V, ValueDisplayed=100pF
C18 C25 C27: library part CMP-0006324-2, "CAP, CERM, 0.01 uF, 50 V, +/- 10%, X7R, AEC-Q200 Grade 1, 0402", Cap_Case=0402, Manufacturer=TDK, Supplier Part Number 1=445-6893-1-ND, TempCo=X7R, Tolerance_%=10%, Value1="0.333065 ohm", Value2=50V, ValueDisplayed=0.01uF
C19 C26: library part CMP-0007964-2, "CAP, CERM, 4.7 uF, 35 V, +/- 10%, X7R, AEC-Q200 Grade 1, 0805", Cap_Case=0805, Manufacturer=TDK, Supplier Part Number 1=810-CGA4J1X7R1V475K125AC, TempCo=X7R, Tolerance_%=10%, Value1="0.002346 ohm", Value2=35V, ValueDisplayed=4.7uF
C23: library part CMP-0007086-4, "CAP, CERM, 0.022 uF, 100 V, +/- 10%, X7R, AEC-Q200 Grade 1, 0603", Cap_Case=0603, Manufacturer=TDK, Supplier Part Number 1=445-5814-1-ND, TempCo=X7R, Tolerance_%=10%, Value1="0.083542 ohm", Value2=100V, ValueDisplayed=0.022uF
C24: library part CMP-0007100-4, "CAP, CERM, 0.033 uF, 100 V, +/- 10%, X7S, AEC-Q200 Grade 1, 0603", Cap_Case=0603, Manufacturer=TDK, Supplier Part Number 1=445-6935-1-ND, TempCo=X7S, Tolerance_%=10%, Value1="0.139637 ohm", Value2=100V, ValueDisplayed=0.033uF
C28: library part CMP-0076705-3, "CAP, CERM, 1 µF, 25 V,+/- 10%, X7R, AEC-Q200 Grade 1, 0603", Cap_Case=1.6x0.8x0.8mm, Manufacturer=TDK, Supplier Part Number 1=445-6931-1-ND, TempCo=X7R, Tolerance_%=10%, Value2=25V, ValueDisplayed=1µF
C29: library part CMP-0006328-2, "CAP, CERM, 0.022 uF, 50 V, +/- 10%, X7R, AEC-Q200 Grade 1, 0402", Cap_Case=0402, Manufacturer=TDK, Supplier Part Number 1=445-6895-1-ND, TempCo=X7R, Tolerance_%=10%, Value1="0.141987 ohm", Value2=50V, ValueDisplayed=0.022uF
C30 C37: library part CMP-0007967-2, "CAP, CERM, 0.22 uF, 50 V, +/- 10%, X7R, AEC-Q200 Grade 1, 0805", Cap_Case=0805, Manufacturer=TDK, Supplier Part Number 1=445-5683-1-ND, TempCo=X7R, Tolerance_%=10%, Value1="0.016949 ohm", Value2=50V, ValueDisplayed=0.22uF
C31 C34 C38 C41: library part CMP-0009302-2, "CAP, CERM, 1 uF, 250 V, +/- 10%, X7R, 1825", Cap_Case=1825, Manufacturer=AVX, Supplier Part Number 1=478-3989-1-ND, TempCo=X7R, Tolerance_%=10%, Value1=Unknown, Value2=250V, ValueDisplayed=1uF
C32 C39: library part CMP-0076706-1, "CAP, CERM, 4.7 µF, 25 V,+/- 10%, X7R, AEC-Q200 Grade 1, 0805", Cap_Case=2x1.25x1.25mm, Manufacturer=TDK, Supplier Part Number 1=445-6967-1-ND, TempCo=X7R, Tolerance_%=10%, Value2=25V, ValueDisplayed=4.7µF
C33 C36 C40 C43: library part CMP-0079151-1, "CAP, CERM, 33 pF, 50 V,+/- 5%, C0G, AEC-Q200 Grade 1, 0402", Cap_Case=0402, Manufacturer=Kemet, Supplier Part Number 1=399-12979-1-ND, TempCo=C0G, Tolerance_%=5%, Value2=50V, ValueDisplayed=33pF
C35 C42: library part CMP-0008797-2, "CAP, CERM, 0.1 uF, 450 V, +/- 20%, X7T, AEC-Q200 Grade 1, 1206", Cap_Case=1206, Manufacturer=TDK, Supplier Part Number 1=445-12959-1-ND, TempCo=X7T, Tolerance_%=20%, Value1=Unknown, Value2=450V, ValueDisplayed=0.1uF
C44: library part CMP-0081512-1, "CAP, CERM, 1 µF, 10 V,+/- 10%, X7R, AEC-Q200 Grade 1, 0603", Cap_Case=0603, Manufacturer=Samsung, Supplier Part Number 1=1276-6825-1-ND, TempCo=X7R, Tolerance_%=10%, Value2=10V, ValueDisplayed=1µF
C45 C46 C47 C48: library part CMP-0007134-5, "CAP, CERM, 2.2 uF, 6.3 V, +/- 10%, X7R, AEC-Q200 Grade 1, 0603", Cap_Case=0603, Manufacturer=MuRata, Supplier Part Number 1=490-5316-1-ND, TempCo=X7R, Tolerance_%=10%, Value1=Unknown, Value2=6.3V, ValueDisplayed=2.2uF
D1 D4 D5 D6 D7: library part CMP-0074797-1, "Diode, Schottky, 100 V, 1 A, AEC-Q101, PowerDI123", Manufacturer="Diodes Inc.", Supplier Part Number 1=DFLS1100Q-7DICT-ND, Value1=1A, Value2=.77V
D2: library part CMP-0005769-2, "Diode, Zener, 16 V, 500 mW, AEC-Q101, SOD-123", Manufacturer="Diodes Inc.", Power_W=500mW, Supplier Part Number 1=BZT52C16-FDICT-ND, Value1=0.5W
D3: library part CMP-0005445-2, "Diode, TVS, Bi, 18 V, 25.2 Vc, AEC-Q101, SMA", Manufacturer=Vishay-Semiconductor, Power_W=3.3W, Supplier Part Number 1=P4SMA18CA-E3/61GICT-ND
D8: library part CMP-0028524-1, "Diode, Schottky, 20 V, 0.5 A, SOD-123", Manufacturer="ON Semiconductor", Supplier Part Number 1=MBR0520LT1GOSCT-ND, Value1=0.5A, Value2=0.385V
D9 D12: library part CMP-0029033-1, "Diode, Ultrafast, 600 V, 1 A, AEC-Q101, SMA", Manufacturer="ON Semiconductor", Supplier Part Number 1=MURA160T3GOSCT-ND, Value1=1A, Value2=1.05V
D10 D11 D13 D14: library part CMP-0080760-1, "Diode, Schottky, 100 V, 0.15 A, AEC-Q101, SOD-123", Manufacturer=Vishay-Semiconductor, Supplier Part Number 1=BAT46W-E3-08CT-ND, Value1=0.15A, Value2=1V
J1: library part CMP-0055472-1, "Conn Term Block, 2POS, 3.81mm, TH", Manufacturer="Phoenix Contact", Supplier Part Number 1=277-1947-ND
J2: library part CMP-0075360-1, "Terminal Block, 6.35mm, 2x1, TH", Color=Green, Current_A=30A, Manufacturer="On-Shore Technology", Supplier Part Number 1=ED2675-ND, Voltage_V=300V
J3: library part CMP-0002339-2, "Header, 100mil, 7x2, Tin, TH", Color=Black, Current_A=3A, Manufacturer="Sullins Connector Solutions", Supplier Part Number 1=S2012E-07-ND, Voltage_V=1.8kV
J4: library part CMP-0055604-2, "Header, 100mil, 6x1, Tin, TH", Color=Black, Current_A=6.3A, Manufacturer=Samtec, Supplier Part Number 1=SAM1035-06-ND, Voltage_V=550V
L1: library part CMP-0061001-2, "Inductor, Shielded, Composite, 2.2 µH, 9.2 A, 0.01 ohm, AEC-Q200 Grade 1, SMD", Manufacturer=Coilcraft, Value1="0.01 ohm", Value2=9.2A, ValueDisplayed=2.2uH
L2: library part CMP-0061500-2, "Inductor, Shielded Drum Core, Ferrite, 27 uH, 2.9 A, 0.05 ohm, SMD", Manufacturer=Coilcraft, Value1="0.05 ohm", Value2=2.9A, ValueDisplayed=27uH
L3: library part CMP-0064681-2, "Inductor, Shielded, Powdered Iron, 22 uH, 0.6 A, 1.04 ohm, AEC-Q200 Grade 1, SMD", Manufacturer="Wurth Elektronik", Supplier Part Number 1=732-6945-1-ND, Value1="1.04 ohm", Value2=0.6A, ValueDisplayed=22uH
L4 L5: library part CMP-0056393-1, "Inductor, Shielded Drum Core, Ferrite, 330 uH, 1.1 A, 0.58 ohm, AEC-Q200 Grade 1, SMD", Manufacturer=Bourns, Value1="0.58 ohm", Value2=1.1A, ValueDisplayed=330uH
L6: library part CMP-0003093-1, "Ferrite Bead, 60 ohm @ 100 MHz, 3 A, 0805", Manufacturer="Wurth Elektronik", Supplier Part Number 1=732-1612-1-ND, Value1="0.025 ohm", Value2=3A, ValueDisplayed="60 ohm"
L7: library part CMP-0003297-1, "Ferrite Bead, 220 ohm @ 100 MHz, 2 A, 0805", Manufacturer="Wurth Elektronik", Supplier Part Number 1=732-6711-1-ND, Value1="0.05 ohm", Value2=2A, ValueDisplayed="220 ohm"
LBL1: library part CMP-0003625-1, "Thermal Transfer Printable Labels, 0.650\" W x 0.200\" H - 10,000 per roll", Manufacturer=Brady, Supplier Part Number 1=97C5133
Logo2: library part CMP-0074839-1
Logo3: library part CMP-0074847-1, "FCC_disclaimer"
Q1: library part CMP-0000041-2, "MOSFET, P-CH, -30 V, -8.5 A, AEC-Q101, 8-PowerVDFN", Alternate Manufacturer=None, Manufacturer="Diodes Inc.", Supplier Part Number 1=DMP3035SFG-7DI-ND, Value2="35.5 nC"
Q2: library part CMP-0080929-1, "MOSFET, N-CH, 100 V, 14 A, AEC-Q101, PowerPAK_SO-8L", Alternate Manufacturer=None, Manufacturer=Vishay-Siliconix, Supplier Part Number 1=SQJA68EP-T1_GE3CT-ND, Value1="0.117 ohm", Value2="4.7 nC"
Q3: library part CMP-0077248-1, "MOSFET, N-CH, 20 V, 2.3 A, AEC-Q101, SOT-23", Alternate Manufacturer=None, Manufacturer="Infineon Technologies", Supplier Part Number 1=BSS806NEH6327XTSA1CT-ND, Value1="? ohm", Value2="1.7 nC"
Q4 Q5 Q6 Q7: library part CMP-0082696-1, "MOSFET, N-CH, 250 V, 5 A, AEC-Q101, DPAK", Alternate Manufacturer=None, Manufacturer="Infineon Technologies", Supplier Part Number 1=IPD5N25S3430ATMA1-ND, Value1="? ohm", Value2="4.7 nC"
R1: library part CMP-0022126-4, "RES, 1.50 k, 1%, 0.1 W, AEC-Q200 Grade 0, 0603", Manufacturer=Vishay-Dale, Power_W=100mW, Supplier Part Number 1=541-1.50KHCT-ND, TempCo="100 ppm/C", Tolerance_%=1%, Value2=0.1W, Value_Code=1k50, ValueDisplayed=1.50k
R2 R7: library part CMP-0022004-4, "RES, 10.0, 1%, 0.25 W, AEC-Q200 Grade 0, 0603", Manufacturer=Vishay-Dale, Power_W=250mW, Supplier Part Number 1=541-10.0SCT-ND, TempCo="100 ppm/C", Tolerance_%=1%, Value2=0.25W, Value_Code=10R0, ValueDisplayed=10.0
R3: library part CMP-0026514-2, "RES, 6.34 k, 1%, 0.063 W, AEC-Q200 Grade 0, 0402", Manufacturer=Vishay-Dale, Power_W=63mW, Supplier Part Number 1=541-6.34KLCT-ND, TempCo="100 ppm/C", Tolerance_%=1%, Value2=0.063W, Value_Code=6k34, ValueDisplayed=6.34k
R4 R13 R19: library part CMP-0081973-1, "RES, 0, 0%, 0.25 W, AEC-Q200 Grade 0, 0603", Manufacturer=Vishay-Dale, Power_W=250mW, Supplier Part Number 1=541-2779-1-ND, Tolerance_%=0%, Value2=0.25W, Value_Code=0
R5 R6: library part CMP-0026435-2, "RES, 511 k, 1%, 0.063 W, AEC-Q200 Grade 0, 0402", Manufacturer=Vishay-Dale, Power_W=63mW, Supplier Part Number 1=541-511KLCT-ND, TempCo="100 ppm/C", Tolerance_%=1%, Value2=0.063W, Value_Code=511k
R8: library part CMP-0017437-3, "RES, 200 k, 1%, 0.25 W, AEC-Q200 Grade 0, 1206", Manufacturer=Panasonic, Power_W=250mW, Supplier Part Number 1=P200KFCT-ND, TempCo="100 ppm/C", Tolerance_%=1%, Value2=0.25W, Value_Code=200k
R9: library part CMP-0021591-3, "RES, 1.69 k, 1%, 0.125 W, AEC-Q200 Grade 0, 0805", Manufacturer=Panasonic, Power_W=125mW, Supplier Part Number 1=P1.69KCCT-ND, TempCo="100 ppm/C", Tolerance_%=1%, Value2=0.125W, Value_Code=1k69, ValueDisplayed=1.69k
R10: library part CMP-0022665-4, "RES, 9.09 k, 1%, 0.1 W, AEC-Q200 Grade 0, 0603", Manufacturer=Vishay-Dale, Power_W=100mW, Supplier Part Number 1=541-9.09KHCT-ND, TempCo="100 ppm/C", Tolerance_%=1%, Value2=0.1W, Value_Code=9k09, ValueDisplayed=9.09k
R11: library part CMP-0022727-3, "RES, 0.05, 1%, 0.1 W, AEC-Q200 Grade 1, 0603", Manufacturer=Panasonic, Power_W=100mW, Supplier Part Number 1=P50LJCT-ND, TempCo="200 ppm/C", Tolerance_%=1%, Value2=0.1W, Value_Code=R050, ValueDisplayed=0.05
R12: library part CMP-0017290-3, "RES, 102 k, 1%, 0.25 W, AEC-Q200 Grade 0, 1206", Manufacturer=Panasonic, Power_W=250mW, Supplier Part Number 1=P102KFCT-ND, TempCo="100 ppm/C", Tolerance_%=1%, Value2=0.25W, Value_Code=102k
R14: library part CMP-0022449-4, "RES, 4.02 k, 1%, 0.1 W, AEC-Q200 Grade 0, 0603", Manufacturer=Vishay-Dale, Power_W=100mW, Supplier Part Number 1=541-4.02KHCT-ND, TempCo="100 ppm/C", Tolerance_%=1%, Value2=0.1W, Value_Code=4k02, ValueDisplayed=4.02k
R15: library part CMP-0026685-1, "RES, 2.40 k, 1%, 0.1 W, AEC-Q200 Grade 0, 0402", Manufacturer=Panasonic, Power_W=100mW, Supplier Part Number 1=P2.40KLCT-ND, TempCo="100 ppm/C", Tolerance_%=1%, Value2=0.1W, Value_Code=2k40, ValueDisplayed=2.40k
R16 R18 R24 R32 R42: library part CMP-0081856-1, "RES, 0, 0%, 0.2 W, AEC-Q200 Grade 0, 0402", Manufacturer=Vishay-Dale, Power_W=200mW, Supplier Part Number 1=541-0.0YBTR-ND, Tolerance_%=0%, Value2=0.2W, Value_Code=0
R17: library part CMP-0022106-4, "RES, 19.6 k, 1%, 0.1 W, AEC-Q200 Grade 0, 0603", Manufacturer=Vishay-Dale, Power_W=100mW, Supplier Part Number 1=541-19.6KHCT-ND, TempCo="100 ppm/C", Tolerance_%=1%, Value2=0.1W, Value_Code=19k6, ValueDisplayed=19.6k
R20: library part CMP-0026557-2, "RES, 7.87 k, 1%, 0.063 W, AEC-Q200 Grade 0, 0402", Manufacturer=Vishay-Dale, Power_W=63mW, Supplier Part Number 1=541-7.87KLCT-ND, TempCo="100 ppm/C", Tolerance_%=1%, Value2=0.063W, Value_Code=7k87, ValueDisplayed=7.87k
R21: library part CMP-0026017-3, "RES, 14.7 k, 1%, 0.063 W, AEC-Q200 Grade 0, 0402", Manufacturer=Vishay-Dale, Power_W=63mW, Supplier Part Number 1=541-14.7KLCT-ND, TempCo="100 ppm/C", Tolerance_%=1%, Value2=0.063W, Value_Code=14k7, ValueDisplayed=14.7k
R22: library part CMP-0026117-2, "RES, 1.50 M, 1%, 0.063 W, AEC-Q200 Grade 0, 0402", Manufacturer=Vishay-Dale, Power_W=63mW, Supplier Part Number 1=541-1.50MLCT-ND, TempCo="100 ppm/C", Tolerance_%=1%, Value2=0.063W, Value_Code=1M50, ValueDisplayed=1.50M
R23: library part CMP-0026046-3, "RES, 174 k, 1%, 0.063 W, AEC-Q200 Grade 0, 0402", Manufacturer=Vishay-Dale, Power_W=63mW, Supplier Part Number 1=541-174KLCT-ND, TempCo="100 ppm/C", Tolerance_%=1%, Value2=0.063W, Value_Code=174k
R25 R33: library part CMP-0026266-2, "RES, 2.21, 1%, 0.063 W, AEC-Q200 Grade 0, 0402", Manufacturer=Vishay-Dale, Power_W=63mW, Supplier Part Number 1=541-2.21LLCT-ND, TempCo="100 ppm/C", Tolerance_%=1%, Value2=0.063W, Value_Code=2R21, ValueDisplayed=2.21
R26 R30 R34 R38: library part CMP-0026357-2, "RES, 3.32, 1%, 0.063 W, AEC-Q200 Grade 0, 0402", Manufacturer=Vishay-Dale, Power_W=63mW, Supplier Part Number 1=541-3.32LLCT-ND, TempCo="100 ppm/C", Tolerance_%=1%, Value2=0.063W, Value_Code=3R32, ValueDisplayed=3.32
R27 R31 R35 R39: library part CMP-0025959-3, "RES, 10.2 k, 1%, 0.063 W, AEC-Q200 Grade 0, 0402", Manufacturer=Vishay-Dale, Power_W=63mW, Supplier Part Number 1=541-10.2KLCT-ND, TempCo="100 ppm/C", Tolerance_%=1%, Value2=0.063W, Value_Code=10k2, ValueDisplayed=10.2k
R28 R29 R36 R37: library part CMP-0026404-2, "RES, 49.9, 1%, 0.063 W, AEC-Q200 Grade 0, 0402", Manufacturer=Vishay-Dale, Power_W=63mW, Supplier Part Number 1=541-49.9LCT-ND, TempCo="100 ppm/C", Tolerance_%=1%, Value2=0.063W, Value_Code=49R9, ValueDisplayed=49.9
R40 R41: library part CMP-0025817-4, "RES, 4.7 k, 5%, 0.1 W, AEC-Q200 Grade 0, 0603", Manufacturer=Vishay-Dale, Power_W=100mW, Supplier Part Number 1=541-4.7KGCT-ND, TempCo="200 ppm/C", Tolerance_%=5%, Value2=0.1W, Value_Code=4k70, ValueDisplayed=4.7k
R43: library part CMP-0026758-1, "RES, 2.20 k, 1%, 0.063 W, AEC-Q200 Grade 0, 0402", Manufacturer="Stackpole Electronics Inc", Power_W=63mW, Supplier Part Number 1=RMCF0402FT2K20CT-ND, TempCo="100 ppm/C", Tolerance_%=1%, Value2=0.063W, Value_Code=2k20, ValueDisplayed=2.20k
R44: library part CMP-0026072-3, "RES, 1.02 k, 1%, 0.063 W, AEC-Q200 Grade 0, 0402", Manufacturer=Vishay-Dale, Power_W=63mW, Supplier Part Number 1=541-1.02KLCT-ND, TempCo="100 ppm/C", Tolerance_%=1%, Value2=0.063W, Value_Code=1k02, ValueDisplayed=1.02k
R45 R46: library part CMP-0018602-3, "RES, 18, 5%, 0.25 W, AEC-Q200 Grade 0, 1206", Manufacturer=Vishay-Dale, Power_W=250mW, Supplier Part Number 1=541-18ECT-ND, TempCo="200 ppm/C", Tolerance_%=5%, Value2=0.25W, Value_Code=18R0, ValueDisplayed=18
TP1 TP2 TP4 TP11: library part CMP-0055147-1, "Test Point, Multipurpose, Red, TH", Color=Red, Manufacturer=Keystone, Supplier Part Number 1=36-5010-ND
TP3 TP9 TP10 TP12 TP14 TP15 TP17 TP18: library part CMP-0003825-1, "1mm Test Point, SMT", Manufacturer=Any
TP5 TP6 TP7 TP8: library part CMP-0055148-1, "Test Point, Multipurpose, Black, TH", Color=Black, Manufacturer=Keystone, Supplier Part Number 1=36-5011-ND
TP13 TP16: library part CMP-0055156-1, "Test Point, Multipurpose, Blue, TH", Color=Blue, Manufacturer=Keystone, Supplier Part Number 1=36-5127-ND
U1: library part CMP-0081538-1, "Automotive Grade 2.2-MHz Wide Input Non-synchronous Boost Controller, DSS0012C (WSON-12)", Alternate Manufacturer="Texas Instruments", Alternate PartNumber=LM5155QDSSRQ1
U2: library part CMP-0013312-4, "300mA High-Voltage Ultra-Low-Iq Low-Dropout (LDO) Regulator, DGN0008D (VSSOP-8)", Alternate Manufacturer="Texas Instruments"
U3: library part CMP-0042688-1, "Automotive Catalog 550 uA/Ch, 3 MHz, Rail-to-Rail Output Operational Amplifier, 2.7 to 16 V, -40 to 125 degC, 8-pin SOIC (D8), Green (RoHS & no Sb/Br)", Manufacturer="Texas Instruments", Rating=Automotive, Total Supply Voltage(Max)(+5V is 5, +/-5V is 10)=16, Total Supply Voltage(Min)(+5V is 5, +/-5V is 10)=2.7
U4: library part CMP-0034799-1, "Automotive Catalog Low Power DC / DC Boost Conveter, 1.8 to 6 V, -40 to 125 degC, 5-pin SOT23 (DBV5), Green (RoHS & no Sb/Br)", Manufacturer="Texas Instruments", Rating=Automotive, Switching Frequency(Max)(kHz)=1000
U5 U6: library part CMP-0065057-2, "620-V High-Side Low-Side Gate Driver with 2.5A Peak Output and RobustDrive, D0008A (SOIC-8)", Alternate Manufacturer="Texas Instruments"
U7: library part CMP-0082224-1, "Piccolo Microcontroller, PT0048A (LQFP-48)", Alternate Manufacturer="Texas Instruments", Alternate PartNumber=TMS320F28027PTQR, Operating Temperature Range="-40 to 125 C"
ZZ1: library part CMP-0003616-3
ZZ2: library part CMP-0077236-1
ZZ3: library part CMP-0077237-1
ZZ4: library part CMP-0077238-1

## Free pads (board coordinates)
  round 60 hole 125: 1(160,160) 1(160,2140) 1(5740,160) 1(5740,2140)

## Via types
v1: diameter 22, hole 10, Top Layer to Bottom Layer, 506 vias
v2: diameter 50, hole 28, Top Layer to Bottom Layer, tented both sides, 22 vias
v3: diameter 22, hole 10, Top Layer to Bottom Layer, tented both sides, 11 vias
v4: diameter 19.68, hole 7.87, Top Layer to Bottom Layer, tented both sides, 8 vias

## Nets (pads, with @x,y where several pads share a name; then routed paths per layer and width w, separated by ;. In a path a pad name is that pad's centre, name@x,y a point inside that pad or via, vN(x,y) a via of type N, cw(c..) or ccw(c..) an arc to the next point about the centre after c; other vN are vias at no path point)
C2000_PWR: L6.2 L7.2 R42.2 R44.1 | length 1003.5
  Top Layer w12: R42.2@740,1423.62 806.38,1423.62 L6.2@810,1420
  Top Layer w25: v2(560,2040) 630.55,2040 L7.2@638.35,2047.8 638.35,2128.35 680,2170 R44.1@726.38,2170 ; v2(700,1490) 740,1450
  Bottom Layer w25: v2(560,2040) 560,1650 700,1510 v2(700,1490)
COMP1: J4.6 U7.9 | length 256.3
  Top Layer w10: U7.9@765.31,1894.14 765.31,2002.42 J4.6@870,2107.12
